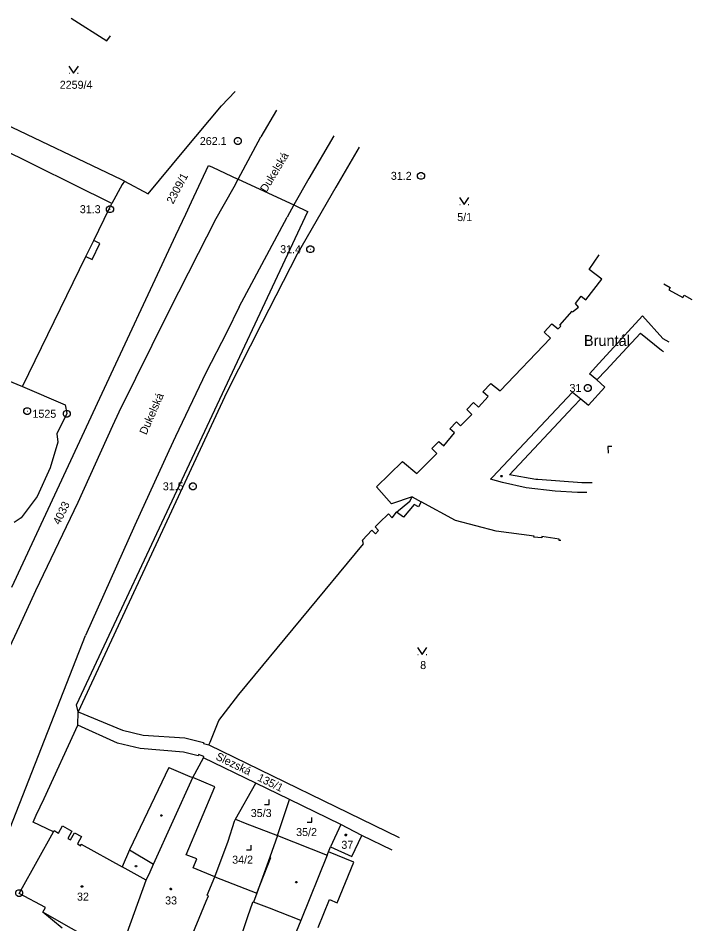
# Model space of a CAD drawing. Extents: x -528274 to -527531, y -1079304 to -1078580.
# Drawn here: x -527673.9 to -527530.9, y -1079170.6 to -1078978.1 of the extents above; entities that cross this region are included whole.
import ezdxf

# ---------------------------------------------------------------- set-up
doc = ezdxf.new("R2010")
doc.units = 0
doc.layers.add('katastrální mapa', color=7, linetype='Continuous')

msp = doc.modelspace()

# ---------------------------------------------------------------- linework, layer by layer
at = {"layer": 'katastrální mapa'}
for p, q in [((-527662.64, -1078978.11), (-527655.05, -1078982.96)), ((-527655.05, -1078982.96), (-527654.33, -1078981.84)), ((-527654, -1079017.49), (-527708.2, -1078990.67)), ((-527651.89, -1079012.5), (-527697.56, -1078990.64)), ((-527663.08, -1078989.78), (-527662.98, -1078989.78)), ((-527661.28, -1078989.78), (-527661.18, -1078989.78)), ((-527630.71, -1078996.75), (-527627.83, -1078993.73)), ((-527638.74, -1079006.27), (-527630.71, -1078996.75)), ((-527619.05, -1078997.67), (-527622.36, -1079003.33)), ((-527627.31, -1079004.22), (-527627.21, -1079004.22)), ((-527627.17, -1079012.34), (-527622.36, -1079003.33)), ((-527606.88, -1079003.13), (-527612.2, -1079012.15)), ((-527646.33, -1079015.43), (-527638.74, -1079006.27)), ((-527601.53, -1079005.54), (-527606.48, -1079014.04)), ((-527637.12, -1079017.15), (-527633.5, -1079009.4)), ((-527633.5, -1079009.4), (-527632.66, -1079009.79)), ((-527632.66, -1079009.79), (-527627.27, -1079012.29)), ((-527588.43, -1079011.62), (-527588.33, -1079011.62)), ((-527651.86, -1079013.49), (-527654, -1079017.49)), ((-527651.36, -1079012.75), (-527651.89, -1079012.5)), ((-527651.36, -1079012.75), (-527651.86, -1079013.49)), ((-527651.36, -1079012.75), (-527646.33, -1079015.43)), ((-527632.13, -1079021.15), (-527628.02, -1079013.93)), ((-527628.02, -1079013.93), (-527627.17, -1079012.34)), ((-527627.27, -1079012.29), (-527627.17, -1079012.34)), ((-527627.17, -1079012.34), (-527615.39, -1079017.81)), ((-527612.2, -1079012.15), (-527615.39, -1079017.81)), ((-527606.48, -1079014.04), (-527614.7, -1079028.27)), ((-527654.56, -1079018.64), (-527654, -1079017.49)), ((-527638.33, -1079019.76), (-527637.12, -1079017.15)), ((-527615.39, -1079017.81), (-527616.82, -1079020.38)), ((-527615.39, -1079017.81), (-527615.1, -1079017.94)), ((-527580.14, -1079017.7), (-527580.04, -1079017.7)), ((-527578.34, -1079017.7), (-527578.24, -1079017.7)), ((-527661.5, -1079124), (-527612.4, -1079019.2)), ((-527657.86, -1079025.39), (-527654.56, -1079018.64)), ((-527654.47, -1079018.7), (-527654.37, -1079018.7)), ((-527640.42, -1079024.23), (-527638.33, -1079019.76)), ((-527615.1, -1079017.94), (-527612.59, -1079019.11)), ((-527612.59, -1079019.11), (-527612.4, -1079019.2)), ((-527632.13, -1079021.15), (-527635.71, -1079028.15)), ((-527626.97, -1079039.42), (-527616.82, -1079020.38)), ((-527659.51, -1079028.75), (-527657.86, -1079025.39)), ((-527656.59, -1079026.02), (-527657.86, -1079025.39)), ((-527657.07, -1079059.93), (-527640.42, -1079024.23)), ((-527658.23, -1079029.38), (-527656.59, -1079026.02)), ((-527611.93, -1079027.2), (-527611.83, -1079027.2)), ((-527673.02, -1079056.4), (-527659.51, -1079028.75)), ((-527659.51, -1079028.75), (-527658.23, -1079029.38)), ((-527635.71, -1079028.15), (-527642.01, -1079040.53)), ((-527614.7, -1079028.27), (-527622.17, -1079042.94)), ((-527552.68, -1079031.49), (-527550.58, -1079028.4)), ((-527550, -1079033.55), (-527552.68, -1079031.49)), ((-527553.4, -1079037.95), (-527550, -1079033.55)), ((-527536.79, -1079034.59), (-527535.51, -1079035.37)), ((-527535.51, -1079035.37), (-527535.76, -1079035.82)), ((-527535.76, -1079035.82), (-527532.81, -1079037.45)), ((-527532.81, -1079037.45), (-527532.5, -1079037)), ((-527532.5, -1079037), (-527530.87, -1079037.86)), ((-527555.59, -1079038.72), (-527554.37, -1079037.21)), ((-527554.95, -1079039.52), (-527555.59, -1079038.72)), ((-527554.37, -1079037.21), (-527553.4, -1079037.95)), ((-527642.01, -1079040.53), (-527652.55, -1079061.8)), ((-527626.97, -1079039.42), (-527629.58, -1079044.84)), ((-527558.91, -1079043.35), (-527556.27, -1079040.37)), ((-527556.27, -1079040.37), (-527556.18, -1079040.48)), ((-527556.18, -1079040.48), (-527554.95, -1079039.52)), ((-527548.21, -1079048.87), (-527541.38, -1079041.34)), ((-527541.38, -1079041.34), (-527537.03, -1079046.15)), ((-527622.17, -1079042.94), (-527629.58, -1079057.61)), ((-527562.22, -1079044.81), (-527560.57, -1079043.07)), ((-527560.86, -1079046.11), (-527562.22, -1079044.81)), ((-527560.57, -1079043.07), (-527559.24, -1079044.15)), ((-527559.24, -1079044.15), (-527558.7, -1079043.54)), ((-527558.7, -1079043.54), (-527558.91, -1079043.35)), ((-527629.58, -1079044.84), (-527634.05, -1079053.46)), ((-527571.6, -1079057.27), (-527560.86, -1079046.11)), ((-527546.55, -1079050.17), (-527541.76, -1079045.03)), ((-527541.76, -1079045.03), (-527537.31, -1079048.66)), ((-527537.03, -1079046.15), (-527535.78, -1079046.89)), ((-527537.31, -1079048.66), (-527536.88, -1079048.91)), ((-527548.21, -1079048.87), (-527550.61, -1079051.51)), ((-527549.07, -1079052.87), (-527546.55, -1079050.17)), ((-527552.61, -1079053.71), (-527550.61, -1079051.51)), ((-527682.12, -1079052.54), (-527673.02, -1079056.4)), ((-527634.05, -1079053.46), (-527640.51, -1079067.01)), ((-527551.03, -1079054.97), (-527552.61, -1079053.71)), ((-527551.03, -1079054.97), (-527549.07, -1079052.87)), ((-527575.27, -1079057.52), (-527573.58, -1079055.72)), ((-527573.58, -1079055.72), (-527571.6, -1079057.27)), ((-527549.32, -1079056.54), (-527551.03, -1079054.97)), ((-527673.02, -1079056.4), (-527663.95, -1079060.24)), ((-527629.58, -1079057.61), (-527661.15, -1079125.47)), ((-527574.14, -1079058.52), (-527575.27, -1079057.52)), ((-527573.23, -1079075.65), (-527556.18, -1079057.57)), ((-527556.18, -1079057.57), (-527554.44, -1079058.99)), ((-527553.01, -1079056.69), (-527552.91, -1079056.69)), ((-527552.81, -1079060.36), (-527549.32, -1079056.54)), ((-527658.42, -1079062.82), (-527657.07, -1079059.93)), ((-527578.65, -1079061.29), (-527577.25, -1079059.79)), ((-527577.25, -1079059.79), (-527576.18, -1079060.79)), ((-527576.18, -1079060.79), (-527574.14, -1079058.52)), ((-527556.08, -1079060.73), (-527554.44, -1079058.99)), ((-527554.44, -1079058.99), (-527552.81, -1079060.36)), ((-527672.03, -1079061.6), (-527671.93, -1079061.6)), ((-527663.56, -1079062.13), (-527665.7, -1079066.45)), ((-527663.95, -1079060.24), (-527663.56, -1079062.13)), ((-527652.55, -1079061.8), (-527653.9, -1079064.76)), ((-527577.61, -1079062.29), (-527578.65, -1079061.29)), ((-527569.6, -1079075.16), (-527556.08, -1079060.73)), ((-527675.28, -1079098.98), (-527658.42, -1079062.82)), ((-527663.63, -1079062.17), (-527663.53, -1079062.17)), ((-527582.27, -1079065.38), (-527580.87, -1079063.91)), ((-527580.87, -1079063.91), (-527579.99, -1079064.75)), ((-527579.99, -1079064.75), (-527577.61, -1079062.29)), ((-527653.9, -1079064.76), (-527661.21, -1079081.01)), ((-527581.25, -1079066.23), (-527582.27, -1079065.38)), ((-527665.7, -1079066.45), (-527665.5, -1079068.19)), ((-527640.51, -1079067.01), (-527641.9, -1079070.03)), ((-527583.56, -1079068.96), (-527581.25, -1079066.23)), ((-527665.5, -1079068.19), (-527667.1, -1079073.63)), ((-527586.09, -1079069.58), (-527584.62, -1079068.07)), ((-527585.02, -1079070.64), (-527586.09, -1079069.58)), ((-527584.62, -1079068.07), (-527583.56, -1079068.96)), ((-527547.88, -1079069.14), (-527548.73, -1079069.15)), ((-527548.73, -1079069.15), (-527548.65, -1079070.56)), ((-527641.9, -1079070.03), (-527649.17, -1079085.82)), ((-527589.24, -1079074.88), (-527585.02, -1079070.64)), ((-527667.1, -1079073.63), (-527669.9, -1079079.76)), ((-527597.85, -1079077.72), (-527592.29, -1079072.29)), ((-527592.29, -1079072.29), (-527589.24, -1079074.88)), ((-527564.01, -1079076.1), (-527569.6, -1079075.16)), ((-527573.64, -1079076.09), (-527573.23, -1079075.65)), ((-527571.08, -1079076.74), (-527573.64, -1079076.09)), ((-527566.06, -1079077.91), (-527571.08, -1079076.74)), ((-527563.58, -1079076.16), (-527564.01, -1079076.1)), ((-527554.23, -1079076.85), (-527563.58, -1079076.16)), ((-527552.06, -1079076.84), (-527554.23, -1079076.85)), ((-527636.85, -1079077.58), (-527636.75, -1079077.58)), ((-527594.66, -1079081.33), (-527597.85, -1079077.72)), ((-527559.88, -1079078.6), (-527566.06, -1079077.91)), ((-527555.12, -1079078.91), (-527559.88, -1079078.6)), ((-527553.19, -1079078.91), (-527555.12, -1079078.91)), ((-527669.9, -1079079.76), (-527673.28, -1079084.26)), ((-527661.21, -1079081.01), (-527670.22, -1079099.8)), ((-527590.27, -1079079.81), (-527594.66, -1079081.33)), ((-527593.61, -1079083.05), (-527590.76, -1079080.75)), ((-527590.76, -1079080.75), (-527590.27, -1079079.81)), ((-527590.27, -1079079.81), (-527588.34, -1079080.87)), ((-527588.34, -1079080.87), (-527588.93, -1079081.94)), ((-527581.04, -1079084.87), (-527588.34, -1079080.87)), ((-527594.51, -1079084.31), (-527593.61, -1079083.05)), ((-527592.06, -1079084.16), (-527593.61, -1079083.05)), ((-527589.81, -1079081.46), (-527592.06, -1079084.16)), ((-527588.93, -1079081.94), (-527589.81, -1079081.46)), ((-527673.28, -1079084.26), (-527674.76, -1079085.26)), ((-527597.16, -1079085.26), (-527595.27, -1079083.44)), ((-527595.27, -1079083.44), (-527594.51, -1079084.31)), ((-527572.39, -1079087.1), (-527581.04, -1079084.87)), ((-527649.17, -1079085.82), (-527659.6, -1079109.31)), ((-527600.77, -1079089.04), (-527598.84, -1079086.92)), ((-527598.84, -1079086.92), (-527598.04, -1079087.65)), ((-527598.12, -1079086.2), (-527597.16, -1079085.26)), ((-527597.37, -1079086.98), (-527598.12, -1079086.2)), ((-527598.04, -1079087.65), (-527597.37, -1079086.98)), ((-527564.35, -1079088.15), (-527572.39, -1079087.1)), ((-527600.58, -1079089.83), (-527600.77, -1079089.04)), ((-527564.39, -1079088.36), (-527564.35, -1079088.15)), ((-527562.75, -1079088.5), (-527564.39, -1079088.36)), ((-527562.72, -1079088.27), (-527562.75, -1079088.5)), ((-527559.05, -1079088.84), (-527562.72, -1079088.27)), ((-527559.03, -1079089.06), (-527559.05, -1079088.84)), ((-527558.72, -1079089.08), (-527559.03, -1079089.06)), ((-527627.09, -1079121.81), (-527600.58, -1079089.83)), ((-527670.22, -1079099.8), (-527673.67, -1079107.35)), ((-527673.67, -1079107.35), (-527684.38, -1079129.98)), ((-527687.3, -1079179.85), (-527659.6, -1079109.31)), ((-527589.07, -1079113.34), (-527588.97, -1079113.34)), ((-527587.27, -1079113.34), (-527587.17, -1079113.34)), ((-527631.27, -1079127.35), (-527627.09, -1079121.81)), ((-527661.15, -1079125.47), (-527661.5, -1079124)), ((-527661.21, -1079128.35), (-527661.15, -1079125.47)), ((-527661.15, -1079125.47), (-527651.73, -1079129.38)), ((-527633.17, -1079131.92), (-527631.27, -1079127.35)), ((-527668.41, -1079143.9), (-527661.21, -1079128.35)), ((-527652.84, -1079132.14), (-527661.21, -1079128.35)), ((-527651.73, -1079129.38), (-527647.38, -1079130.42)), ((-527647.38, -1079130.42), (-527638.52, -1079131.05)), ((-527638.52, -1079131.05), (-527634.53, -1079131.98)), ((-527648.03, -1079133.31), (-527652.84, -1079132.14)), ((-527638.8, -1079134.05), (-527648.03, -1079133.31)), ((-527634.53, -1079131.98), (-527634.58, -1079132.24)), ((-527634.58, -1079132.24), (-527633.4, -1079132.48)), ((-527633.4, -1079132.48), (-527633.17, -1079131.92)), ((-527633.4, -1079132.48), (-527593.03, -1079152.19)), ((-527635.68, -1079134.87), (-527638.8, -1079134.05)), ((-527636.82, -1079139.48), (-527634.54, -1079135.24)), ((-527635.63, -1079134.67), (-527635.68, -1079134.87)), ((-527635.6, -1079134.56), (-527635.63, -1079134.67)), ((-527634.49, -1079135), (-527635.6, -1079134.56)), ((-527634.54, -1079135.24), (-527634.49, -1079135)), ((-527623.46, -1079140.63), (-527634.54, -1079135.24)), ((-527641.91, -1079137.31), (-527650.26, -1079154.85)), ((-527641.91, -1079137.31), (-527637.46, -1079139.21)), ((-527645.15, -1079157.87), (-527636.82, -1079139.48)), ((-527637.46, -1079139.21), (-527636.82, -1079139.48)), ((-527632.16, -1079141.45), (-527636.82, -1079139.48)), ((-527627.73, -1079148.27), (-527623.46, -1079140.63)), ((-527616.3, -1079144.11), (-527623.46, -1079140.63)), ((-527638.26, -1079155.86), (-527632.16, -1079141.45)), ((-527670.06, -1079147.46), (-527668.41, -1079143.9)), ((-527618.85, -1079151.75), (-527616.3, -1079144.11)), ((-527605.39, -1079149.42), (-527616.3, -1079144.11)), ((-527670.75, -1079148.94), (-527670.06, -1079147.46)), ((-527629.34, -1079152.94), (-527627.97, -1079148.71)), ((-527627.97, -1079148.71), (-527627.73, -1079148.27)), ((-527627.73, -1079148.27), (-527625.68, -1079149.12)), ((-527666.44, -1079151.01), (-527670.75, -1079148.94)), ((-527665.34, -1079151.27), (-527664.47, -1079149.73)), ((-527664.47, -1079149.73), (-527662.49, -1079150.84)), ((-527625.68, -1079149.12), (-527618.85, -1079151.75)), ((-527605.39, -1079149.42), (-527607.58, -1079154.15)), ((-527600.92, -1079151.76), (-527605.39, -1079149.42)), ((-527673.31, -1079163.43), (-527666.44, -1079151.01)), ((-527666.44, -1079151.01), (-527666.29, -1079150.74)), ((-527666.29, -1079150.74), (-527665.34, -1079151.27)), ((-527662.49, -1079150.84), (-527663.36, -1079152.39)), ((-527663.36, -1079152.39), (-527662.8, -1079152.7)), ((-527662.8, -1079152.7), (-527661.94, -1079151.18)), ((-527661.94, -1079151.18), (-527660.46, -1079152.01)), ((-527660.46, -1079152.01), (-527661.32, -1079153.53)), ((-527618.85, -1079151.75), (-527620.46, -1079156.36)), ((-527618.85, -1079151.75), (-527608.3, -1079155.95)), ((-527603.05, -1079156.25), (-527600.92, -1079151.76)), ((-527594.5, -1079154.89), (-527600.92, -1079151.76)), ((-527661.32, -1079153.53), (-527660.6, -1079153.94)), ((-527660.6, -1079153.94), (-527660.51, -1079153.6)), ((-527660.51, -1079153.6), (-527651.85, -1079158.46)), ((-527632.15, -1079160.57), (-527629.34, -1079152.94)), ((-527608.02, -1079155.24), (-527607.58, -1079154.15)), ((-527607.58, -1079154.15), (-527603.05, -1079156.25)), ((-527650.26, -1079154.85), (-527651.85, -1079158.46)), ((-527650.26, -1079154.85), (-527645.15, -1079157.87)), ((-527635.98, -1079156.76), (-527638.26, -1079155.86)), ((-527620.46, -1079156.36), (-527623.22, -1079164.03)), ((-527608.3, -1079155.95), (-527613.89, -1079169.85)), ((-527608.3, -1079155.95), (-527608.02, -1079155.24)), ((-527602.61, -1079157.45), (-527608.02, -1079155.24)), ((-527645.9, -1079159.51), (-527645.15, -1079157.87)), ((-527636.74, -1079158.62), (-527635.98, -1079156.76)), ((-527606.15, -1079166.05), (-527602.61, -1079157.45)), ((-527646.74, -1079161.26), (-527651.85, -1079158.46)), ((-527646.74, -1079161.26), (-527645.9, -1079159.51)), ((-527632.15, -1079160.57), (-527636.74, -1079158.62)), ((-527652.06, -1079175.97), (-527646.74, -1079161.26)), ((-527633.76, -1079164.43), (-527632.15, -1079160.57)), ((-527632.15, -1079160.57), (-527623.22, -1079164.03)), ((-527673.74, -1079164.01), (-527673.64, -1079164.01)), ((-527673.69, -1079164.1), (-527673.31, -1079163.43)), ((-527668.08, -1079167.1), (-527673.69, -1079164.1)), ((-527623.22, -1079164.03), (-527623.97, -1079165.94)), ((-527640.28, -1079181.04), (-527633.98, -1079165.72)), ((-527633.98, -1079165.72), (-527633.52, -1079164.59)), ((-527633.52, -1079164.59), (-527633.76, -1079164.43)), ((-527624.15, -1079165.99), (-527625.24, -1079169.02)), ((-527623.97, -1079165.94), (-527624.15, -1079165.99)), ((-527620.53, -1079167.22), (-527623.97, -1079165.94)), ((-527610.22, -1079171.32), (-527607.78, -1079165.4)), ((-527607.78, -1079165.4), (-527606.15, -1079166.05)), ((-527668.69, -1079168.06), (-527668.08, -1079167.1)), ((-527613.89, -1079169.85), (-527620.53, -1079167.22)), ((-527652.61, -1079177.19), (-527668.69, -1079168.06)), ((-527664.55, -1079171.47), (-527668.69, -1079168.06)), ((-527625.24, -1079169.02), (-527630.3, -1079184.48)), ((-527613.89, -1079169.85), (-527621.25, -1079187.49))]:
    msp.add_line(p, q, dxfattribs=at)
for points in [[(-527663.13, -1078988.28), (-527662.13, -1078989.78), (-527661.13, -1078988.28)], [(-527580.19, -1079016.2), (-527579.19, -1079017.7), (-527578.19, -1079016.2)], [(-527589.12, -1079111.84), (-527588.12, -1079113.34), (-527587.12, -1079111.84)], [(-527621.62, -1079145.15), (-527620.62, -1079145.15), (-527620.62, -1079144.15)], [(-527612.53, -1079148.96), (-527611.53, -1079148.96), (-527611.53, -1079147.96)], [(-527625.46, -1079154.8), (-527624.46, -1079154.8), (-527624.46, -1079153.8)], [(-527623.22, -1079164.03), (-527620.27, -1079156.43), (-527620.46, -1079156.36)]]:
    msp.add_lwpolyline(points, dxfattribs=at)
for points in [[(-527627.07, -1079003.5), (-527626.73, -1079003.69), (-527626.54, -1079004.03), (-527626.54, -1079004.42), (-527626.73, -1079004.76), (-527627.07, -1079004.95), (-527627.46, -1079004.95), (-527627.8, -1079004.76), (-527627.99, -1079004.42), (-527627.99, -1079004.03), (-527627.8, -1079003.69), (-527627.46, -1079003.5)], [(-527588.19, -1079010.9), (-527587.85, -1079011.09), (-527587.66, -1079011.43), (-527587.66, -1079011.82), (-527587.85, -1079012.16), (-527588.19, -1079012.35), (-527588.58, -1079012.35), (-527588.92, -1079012.16), (-527589.11, -1079011.82), (-527589.11, -1079011.43), (-527588.92, -1079011.09), (-527588.58, -1079010.9)], [(-527654.23, -1079017.98), (-527653.89, -1079018.17), (-527653.7, -1079018.51), (-527653.7, -1079018.9), (-527653.89, -1079019.24), (-527654.23, -1079019.43), (-527654.62, -1079019.43), (-527654.96, -1079019.24), (-527655.15, -1079018.9), (-527655.15, -1079018.51), (-527654.96, -1079018.17), (-527654.62, -1079017.98)], [(-527611.69, -1079026.48), (-527611.35, -1079026.67), (-527611.16, -1079027.01), (-527611.16, -1079027.4), (-527611.35, -1079027.74), (-527611.69, -1079027.93), (-527612.08, -1079027.93), (-527612.42, -1079027.74), (-527612.61, -1079027.4), (-527612.61, -1079027.01), (-527612.42, -1079026.67), (-527612.08, -1079026.48)], [(-527552.77, -1079055.97), (-527552.43, -1079056.16), (-527552.24, -1079056.5), (-527552.24, -1079056.89), (-527552.43, -1079057.23), (-527552.77, -1079057.42), (-527553.16, -1079057.42), (-527553.5, -1079057.23), (-527553.69, -1079056.89), (-527553.69, -1079056.5), (-527553.5, -1079056.16), (-527553.16, -1079055.97)], [(-527671.79, -1079060.88), (-527671.45, -1079061.07), (-527671.26, -1079061.41), (-527671.26, -1079061.8), (-527671.45, -1079062.14), (-527671.79, -1079062.33), (-527672.18, -1079062.33), (-527672.52, -1079062.14), (-527672.71, -1079061.8), (-527672.71, -1079061.41), (-527672.52, -1079061.07), (-527672.18, -1079060.88)], [(-527663.39, -1079061.45), (-527663.05, -1079061.64), (-527662.86, -1079061.98), (-527662.86, -1079062.37), (-527663.05, -1079062.71), (-527663.39, -1079062.9), (-527663.78, -1079062.9), (-527664.12, -1079062.71), (-527664.31, -1079062.37), (-527664.31, -1079061.98), (-527664.12, -1079061.64), (-527663.78, -1079061.45)], [(-527571.2, -1079075.28), (-527571.11, -1079075.43), (-527571.2, -1079075.58), (-527571.38, -1079075.58), (-527571.47, -1079075.43), (-527571.38, -1079075.28)], [(-527636.61, -1079076.86), (-527636.27, -1079077.05), (-527636.08, -1079077.39), (-527636.08, -1079077.78), (-527636.27, -1079078.12), (-527636.61, -1079078.31), (-527637, -1079078.31), (-527637.34, -1079078.12), (-527637.53, -1079077.78), (-527637.53, -1079077.39), (-527637.34, -1079077.05), (-527637, -1079076.86)], [(-527643.4, -1079147.36), (-527643.31, -1079147.51), (-527643.4, -1079147.66), (-527643.58, -1079147.66), (-527643.67, -1079147.51), (-527643.58, -1079147.36)], [(-527604.32, -1079151.5), (-527604.22, -1079151.52), (-527604.17, -1079151.61), (-527604.15, -1079151.67), (-527604.17, -1079151.76), (-527604.25, -1079151.83), (-527604.32, -1079151.84), (-527604.41, -1079151.81), (-527604.47, -1079151.75), (-527604.49, -1079151.67), (-527604.47, -1079151.58), (-527604.39, -1079151.51)], [(-527648.8, -1079158.13), (-527648.71, -1079158.28), (-527648.8, -1079158.43), (-527648.98, -1079158.43), (-527649.07, -1079158.28), (-527648.98, -1079158.13)], [(-527614.76, -1079161.56), (-527614.67, -1079161.71), (-527614.76, -1079161.86), (-527614.94, -1079161.86), (-527615.03, -1079161.71), (-527614.94, -1079161.56)], [(-527673.5, -1079163.29), (-527673.16, -1079163.48), (-527672.97, -1079163.82), (-527672.97, -1079164.21), (-527673.16, -1079164.55), (-527673.5, -1079164.74), (-527673.89, -1079164.74), (-527674.23, -1079164.55), (-527674.42, -1079164.21), (-527674.42, -1079163.82), (-527674.23, -1079163.48), (-527673.89, -1079163.29)], [(-527660.36, -1079162.44), (-527660.26, -1079162.46), (-527660.21, -1079162.55), (-527660.19, -1079162.61), (-527660.21, -1079162.7), (-527660.29, -1079162.77), (-527660.36, -1079162.78), (-527660.45, -1079162.75), (-527660.51, -1079162.69), (-527660.53, -1079162.61), (-527660.51, -1079162.52), (-527660.43, -1079162.45)], [(-527641.5, -1079162.96), (-527641.4, -1079162.98), (-527641.35, -1079163.07), (-527641.33, -1079163.13), (-527641.35, -1079163.22), (-527641.43, -1079163.29), (-527641.5, -1079163.3), (-527641.59, -1079163.27), (-527641.65, -1079163.21), (-527641.67, -1079163.13), (-527641.65, -1079163.04), (-527641.57, -1079162.97)]]:
    msp.add_lwpolyline(points, close=True, dxfattribs=at)

# ---------------------------------------------------------------- texts
for s, height, p in [('2259/4', 1.7, (-527665.08, -1078993.12)), ('262.1', 1.7, (-527635.34, -1079005.07)), ('31.2', 1.7, (-527594.78, -1079012.47)), ('31.3', 1.7, (-527660.82, -1079019.55)), ('5/1', 1.7, (-527580.69, -1079021.23)), ('31.4', 1.7, (-527618.28, -1079028.05)), ('Bruntál', 2.3, (-527553.78, -1079047.76)), ('31', 1.7, (-527556.85, -1079057.54)), ('1525', 1.7, (-527670.87, -1079063.02)), ('31.5', 1.7, (-527643.2, -1079078.43)), ('8', 1.7, (-527588.55, -1079116.41)), ('35/3', 1.7, (-527624.52, -1079147.85)), ('35/2', 1.7, (-527614.89, -1079151.89)), ('37', 1.7, (-527605.29, -1079154.6)), ('34/2', 1.7, (-527628.47, -1079157.76)), ('32', 1.7, (-527661.42, -1079165.61)), ('33', 1.7, (-527642.71, -1079166.42))]:
    msp.add_text(s, height=height, dxfattribs=at).set_placement(p)
for s, rotation, p in [('Dukelská', 59.0147, (-527621.21, -1079015.27)), ('2309/1', 62.2232, (-527641.01, -1079017.74)), ('Dukelská', 66.2339, (-527646.7, -1079066.77)), ('4033', 64.3432, (-527665.09, -1079085.89)), ('Slezská', 334.0344, (-527632.12, -1079135.55)), ('135/1', 333.8625, (-527623.26, -1079140.04))]:
    msp.add_text(s, height=1.7, rotation=rotation, dxfattribs=at).set_placement(p)

doc.saveas('drawing.dxf')
